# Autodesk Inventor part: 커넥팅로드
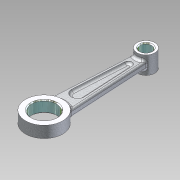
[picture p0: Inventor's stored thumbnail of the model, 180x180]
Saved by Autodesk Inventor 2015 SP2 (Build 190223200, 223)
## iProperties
Manager: KYOUNG IL JANG
Company: 한국ATC센터
Created: 2012-10
Part Number: 커넥팅로드
Document SubType Name: Modeling
Density: 1 g/cm^3
Checked By: KYOUNG IL JANG
Vendor: CBT Solutions
Designer: KYOUNG IL JANG
Material: 일반
Appearance: _시험_알루미늄 표면거칠기
Author: KYOUNG IL JANG
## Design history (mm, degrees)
sketch "스케치1"
  geometry: L1 (-19.879, 82.758)-(-19.879, 197.758); L2 (-27.379, 191.144)-(-32.379, 99.633); L3 (-12.379, 191.144)-(-7.379, 99.633); C1 r 14 at (-19.879, 82.758); C2 r 6.5 at (-19.879, 197.758); A1 r 19 centre (-19.879, 82.758) between (-20.11, 101.757) and (-19.649, 63.76) reference; A2 r 21 centre (-19.879, 82.758) between (-32.379, 99.633) and (-7.379, 99.633); A3 r 10 centre (-19.879, 197.758) between (-27.379, 191.144) and (-12.379, 191.144); 1 further point
  constraints: 6 end point, 4 centre point, 4 coincident, 4 point on circle, 2 horizontal alignment, 1 equal length, 1 vertical
  dimensions: "d0" = 28 diameter of C1; "d1" = 42 diameter of A2; "d4" = 115 distance of L1.end C1.centre; "d5" = 20 diameter of A3; "d6" = 13 diameter of C2; "d7" = 25 distance of L3.end L2.end; "d8" = 15 distance of L3.start L2.start
  node "참조1"
extrude "돌출1" new body sketch "스케치1" stored distance "d2" = 13; taper "d3" = 0 deg
extrude "돌출2" join sketch "스케치1" stored distance "d9" = 20; taper "d10" = 0 deg
extrude "돌출3" join sketch "스케치1" stored distance "d11" = 8; taper "d12" = 0 deg
sketch "스케치2"
  geometry: L1 (7.379, 99.633)-(12.379, 191.144) reference; L2 (27.379, 191.144)-(32.379, 99.633) reference; L3 (27.197, 121.158)-(24.092, 177.989); L4 (15.667, 177.989)-(12.561, 121.158); A1 r 21 centre (19.879, 82.758) between (7.379, 99.633) and (32.379, 99.633) reference; A2 r 7.329 centre (19.879, 120.758) between (12.561, 121.158) and (27.197, 121.158); A3 r 4.219 centre (19.879, 177.758) between (24.092, 177.989) and (15.667, 177.989); A4 r 10 centre (19.879, 197.758) between (12.379, 191.144) and (27.379, 191.144) reference; 2 further points
  constraints: 4 end point, 4 point on circle, 4 tangent, 2 centre point, 2 parallel, 1 coincident, 3 other
  dimensions: "d16" = 38 distance of A2.centre A1.centre; "d17" = 4 distance between parallel lines of L2 L3; "d18" = 4 distance between parallel lines of L4 L1; "d25" = 20 distance of A3.centre A4.centre
extrude "돌출4" cut sketch "스케치2" distance "d19" = 5; taper "d20" = 0 deg
fillet "모깎기1" dims "d21" = 2
fillet "모깎기2" dims "d22" = 3
fillet "모깎기3" dims "d23" = 3
chamfer "모따기1" distance "d26" = 1; stored, may be unused: second distance "d27" = 2, angle "d28" = 45 deg
chamfer "모따기2" distance "d29" = 1; stored, may be unused: second distance "d30" = 2, angle "d31" = 45 deg
node "솔리드1"
mirror "대칭1"
other parameters: "d13" = 5, "d14" = 5
